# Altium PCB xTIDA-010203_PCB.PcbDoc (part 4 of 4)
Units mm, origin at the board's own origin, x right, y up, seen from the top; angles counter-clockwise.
Board outline 200 x 130 mm, 4 copper layers (Top Layer, Signal Layer 1, Signal Layer 2, Bottom Layer), stack 1.588 mm thick; 249 components, 140 nets, 768 pads, 520 vias.
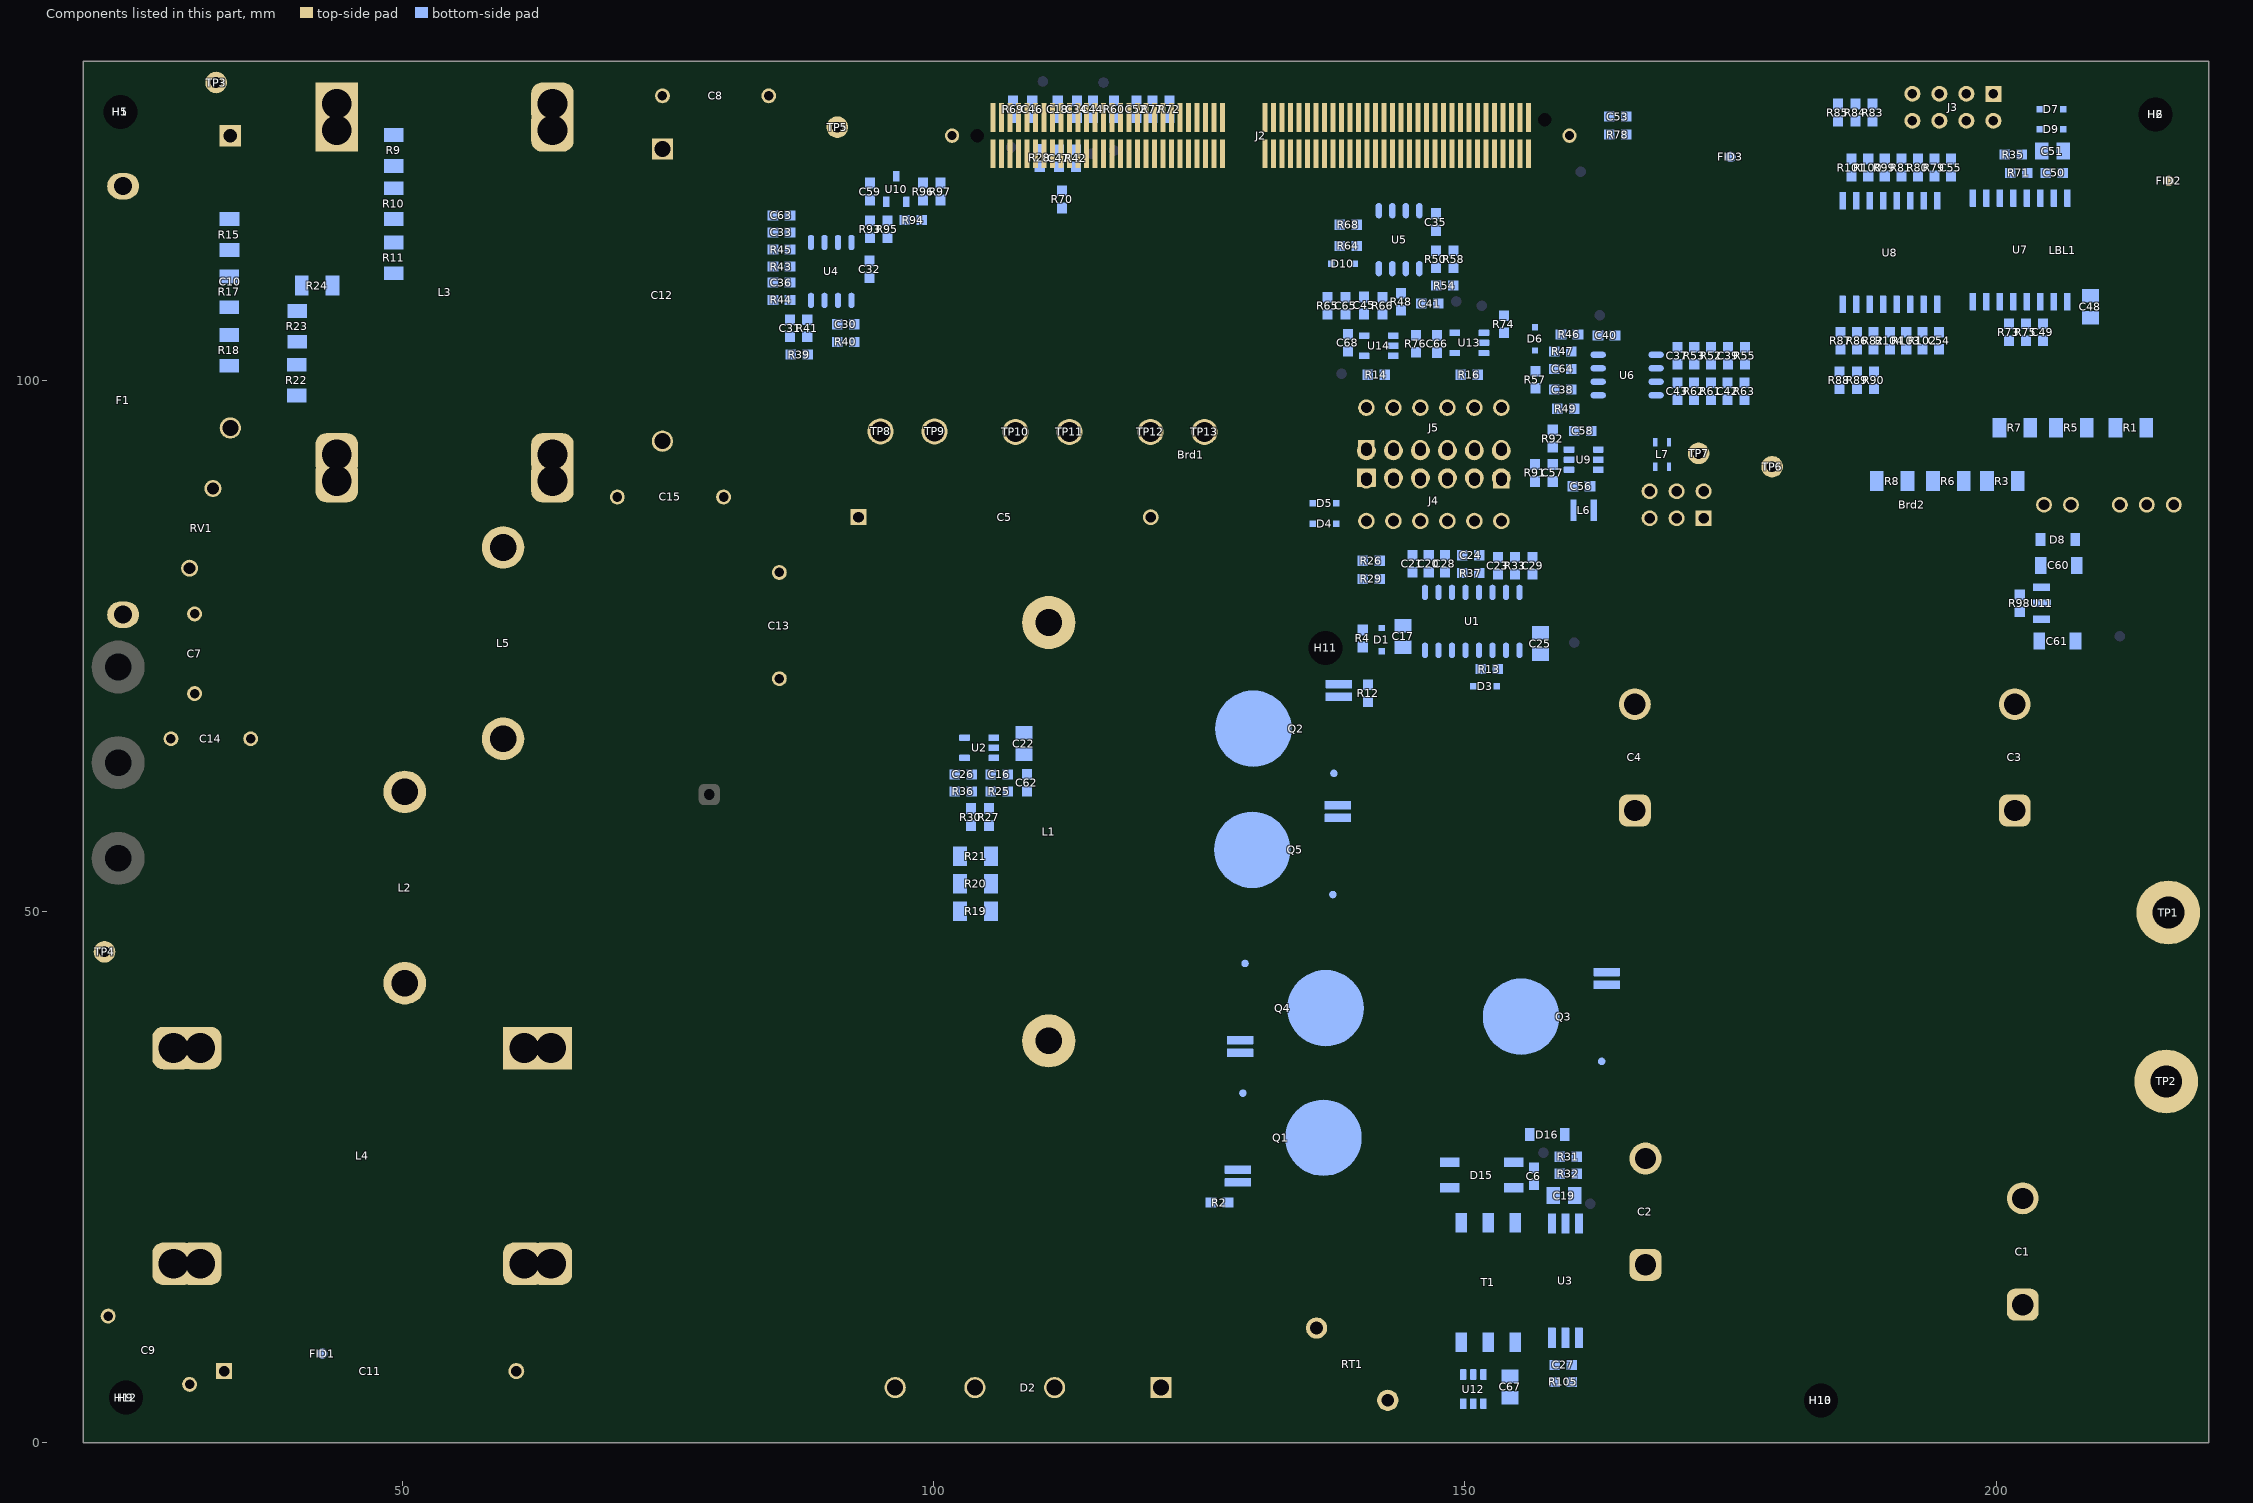
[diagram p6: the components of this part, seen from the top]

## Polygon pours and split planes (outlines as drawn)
NetD2_2 on Bottom Layer "BOTTOM_LAYER_NETD2_2_P189" (solid, remove dead copper, pour order 189): 134.3,76 124.4,76 104.8,56.4 104.8,17.083 108.444,4 115,4 115,12.4 130.2,27.6 130.2,47.2 134.3,51.3
NetC7_1 on Bottom Layer "BOTTOM_LAYER_NETC7_1_P096" (solid, remove dead copper, pour order 96): 20.5,83.5 23.1,86.1 29.9,86.1 32,84 32,77.9 24.5,70.4 20.5,70.4
GND-c on Bottom Layer "BOTTOM_LAYER_GND-C_P219" (solid, remove dead copper, pour order 219): 54.3,20.1 59.2,25 66,25 74.9,33.9 74.9,66.8 83.1,75 100.4,75 103.3,72.1 103.3,18.1 98,12.8 77.7,12.8 68.9,4 57.2,4 54.3,6.9
B+ on Bottom Layer "BOTTOM_LAYER_B+_P197" (solid, remove dead copper, pour order 197): 164.5,10.707 175.493,10.707 175.6,10.752 207.9,10.752 207.9,18.001 201.032,17.998 198,21.03 198,26 200.1,28.1 217.1,28.1 219,30 219,40.497 210.691,40.509 208,43.2 208,62.5 163.5,62.5 162.7,61.7 162.7,33 167.997,33 172,28.997 172,25 167.9,20.9 164.5,20.9
B- on Bottom Layer "BOTTOM_LAYER_B-_P193" (solid, remove dead copper, pour order 193): 137.05,50.004 159.396,50.004 159.396,62.096 163.3,66 207.9,66 208,65.9 208,72 207,73 158.492,73 137.05,69.642
B1+ on Bottom Layer "BOTTOM_LAYER_B1+_P187" (solid, remove dead copper, pour order 187): 159.466,47 159.466,32.813 158.653,32 148.6,32 144.9,28.3 144.9,12.9 134.9,2.9 119.1,2.9 119.1,9.3 132.7,22.9 132.7,46.8 132.9,47
AC-L on Bottom Layer "BOTTOM_LAYER_AC-L_P122" (solid, remove dead copper, pour order 122): 27,21 36,21 38,19 38,4 36,2 29,2 27,4 27,14.002 25.002,16 25.002,19.002
no net on Bottom Layer "BOTTOM_LAYER_NONET_P120" (solid, remove dead copper, pour order 120): 24.033,40
NetL2_2 on Bottom Layer "BOTTOM_LAYER_NETL2_2_P119" (solid, remove dead copper, pour order 119): 51.9,47.031 31.056,47.031 24.9,40.875 24.9,32.2 26.1,31 43,31 53,41 53,46
NetC8_1 on Bottom Layer "BOTTOM_LAYER_NETC8_1_P116" (solid, remove dead copper, pour order 116): 59.1,116 78,116 78,128 77,129 61.1,129 59.1,127
NetC8_1 on Bottom Layer "BOTTOM_LAYER_NETC8_1_P115" (solid, remove dead copper, pour order 115): 49.9,86.9 49.9,103.4 62.5,103.4 62.5,100.1 58.2,95.8 58.2,91.3 54,87.1 54,56.8 53.1,55.9 44,55.9 44,81
NetL4_1 on Bottom Layer "BOTTOM_LAYER_NETL4_1_P118" (solid, remove dead copper, pour order 118): 59,70.048 67.952,70.048 70,68 70,37 66.1,33.1 58.9,33.1 57.4,34.6 57.4,68.5 58.9,70
NetC10_2 on Bottom Layer "BOTTOM_LAYER_NETC10_2_P111" (solid, remove dead copper, pour order 111): 21,58.1 27.279,58.1 34.7,65.521 34.7,85.257 29.995,89.962 29.995,97 45,97 46.3,95.7 46.3,88.5 40.6,82.8 40.6,57.6 35.6,52.6 21,52.6
NetC12_2 on Bottom Layer "BOTTOM_LAYER_NETC12_2_P108" (solid, remove dead copper, pour order 108): 57.4,85.8 61.8,90.2 61.8,95.5 63.2,96.9 74.1,96.9 76,95 76,92.1 64.9,81 57.4,81
NetC10_1 on Bottom Layer "BOTTOM_LAYER_NETC10_1_P103" (solid, remove dead copper, pour order 103): 21,114.8 21,121 29,129 46.1,129 47,128.1 47,120 41.8,114.8
B- on Bottom Layer "BOTTOM_LAYER_B-_P093" (solid, remove dead copper, pour order 93): 134.304,33.019
GND-c on Signal Layer 2 "SIGNAL_LAYER_2_GND-C_P195" (solid, remove dead copper, pour order 195): 128.9,19.1 128.9,63.706 134,68.806 134,82 125,82 123,80 115.7,72.7 80.8,72.7 75,66.9 75,34 66,25 59,25 57,23 57,5.2 58.2,4 74,4 89.1,19.1
NetC7_1 on Signal Layer 2 "SIGNAL_LAYER_2_NETC7_1_P097" (solid, remove dead copper, pour order 97): 20.5,83.5 23.1,86.1 29.9,86.1 32,84 32,77.9 24.5,70.4 20.5,70.4
B1+ on Signal Layer 2 "SIGNAL_LAYER_2_B1+_P221" (solid, remove dead copper, pour order 221): 159.5,37.9 159.5,67.6 155.2,71.9 140,71.9 132.5,64.4 132.5,24.9 135.4,22 150.8,22 159.4,30.6
B- on Signal Layer 2 "SIGNAL_LAYER_2_B-_P199" (solid, remove dead copper, pour order 199): 164,26 164,52.8 170.3,59.1 170.3,62.5 166.8,66 163,66 161.2,67.8 161.2,72 208.7,72 208.7,65.5 199.5,65.5 198,64 198,41.4 207,32.4 207,17 173,17
AGND-s on Signal Layer 2 "SIGNAL_LAYER_2_AGND-S_P173" (solid, remove dead copper, pour order 173): 183.5,129 209,129 210,128 210,116.047 209,115.047 184.842,115.047 183.5,116.389
NetL2_2 on Signal Layer 2 "SIGNAL_LAYER_2_NETL2_2_P130" (solid, remove dead copper, pour order 130): 51.9,47.031 31.056,47.031 24.9,40.875 24.9,32.2 26.1,31 43,31 53,41 53,46
NetL4_1 on Signal Layer 2 "SIGNAL_LAYER_2_NETL4_1_P129" (solid, remove dead copper, pour order 129): 59,70.048 67.952,70.048 70,68 70,35.1 68,33.1 58.9,33.1 57.4,34.6 57.4,68.5 58.9,70
NetC8_1 on Signal Layer 2 "SIGNAL_LAYER_2_NETC8_1_P114" (solid, remove dead copper, pour order 114): 61.1,129 77,129 78,128 78,115.6 78,107.5 69,98.5 63.3,98.5 60.5,95.7 60.5,90.7 56,86.2 56,58.8 53.1,55.9 45.1,55.9 43,58 43,83.1 47.7,87.8 47.7,106.7 59.1,118.1 59.1,127
NetC10_2 on Signal Layer 2 "SIGNAL_LAYER_2_NETC10_2_P110" (solid, remove dead copper, pour order 110): 21,60 28,60 34,66 34,85.957 29.995,89.962 29.995,97 45,97 46.3,95.7 46.3,88.5 41.9,84.1 41.9,55.9 36,50 21,50
NetC12_2 on Signal Layer 2 "SIGNAL_LAYER_2_NETC12_2_P107" (solid, remove dead copper, pour order 107): 57.4,85.8 61.8,90.2 61.8,95.5 63.2,96.9 75,96.9 76,95.9 76,89.9 67.1,81 57.4,81
NetC10_1 on Signal Layer 2 "SIGNAL_LAYER_2_NETC10_1_P102" (solid, remove dead copper, pour order 102): 21,114.8 21,121 29,129 46.1,129 47,128.1 47,120 41.8,114.8
NetC7_1 on Top Layer "TOP_LAYER_NETC7_1_P098" (solid, remove dead copper, pour order 98): 20.5,83.5 23.1,86.1 29.9,86.1 32,84 32,77.9 24.5,70.4 20.5,70.4
AGND-s on Top Layer "TOP_LAYER_AGND-S_P171" (solid, remove dead copper, pour order 171): 183.5,129 209,129 210,128 210,116.047 209,115.047 184.842,115.047 183.5,116.389
GND-c on Top Layer "TOP_LAYER_GND-C_P167" (solid, remove dead copper, pour order 167): 91.204,127.254 177.5,127.254 177.5,114.7 182.8,109.4 210.934,109.4 212.1,108.234 212.1,99.2 210,97.1 203.6,97.1 186.5,80 129.461,80 128.961,80.5 128.961,87.961 131.7,90.7 131.7,96.978 126.678,102 86,102 85,103 85,121.05
B1+ on Top Layer "TOP_LAYER_B1+_P185" (solid, remove dead copper, pour order 185): 98.4,35.4 90.1,43.7 90.1,89.145 91.055,90.1 99.2,90.1 102.5,86.8 102.5,74.1 114.7,61.9 159.4,61.9 159.4,35.4
B- on Top Layer "TOP_LAYER_B-_P229" (solid, remove dead copper, pour order 229): 133.7,16.7 158.7,16.7 163.3,21.3 169,21.3 172.6,17.7 207,17.7 207,32.231 197,42.231 197,61.4 201,65.4 208.7,65.4 208.7,72 161.2,72 161.2,67.8 161.9,67.1 164.8,67.1 170.5,61.4 170.5,57.5 163.6,50.6 163.6,34.6 160.9,31.9 99.1,31.9 93,25.8 93,3.05 93.9,2.15 99.55,2.15 100,2.6 100,6.6 105.1,11.7 128.7,11.7
GND-c on Top Layer "TOP_LAYER_GND-C_P211" (solid, remove dead copper, pour order 211): 66.3,22 57.3,22 54.3,19 54.3,4 56.3,2 63.3,2 65.3,4 65.3,14.002 67.298,16 67.298,21.002
AC-L on Top Layer "TOP_LAYER_AC-L_P123" (solid, remove dead copper, pour order 123): 26,22 35,22 38,19 38,4 36,2 29,2 27,4 27,14.002 25.002,16 25.002,21.002
NetL2_2 on Top Layer "TOP_LAYER_NETL2_2_P121" (solid, remove dead copper, pour order 121): 51.9,47.031 31.031,47.031 24.9,40.9 24.9,31 42.9,31 53,41.1 53,46
NetL4_1 on Top Layer "TOP_LAYER_NETL4_1_P117" (solid, remove dead copper, pour order 117): 59,70.048 67.952,70.048 70,68 70,35.1 68,33.1 58.9,33.1 57.4,34.6 57.4,68.5 58.9,70
NetC10_2 on Top Layer "TOP_LAYER_NETC10_2_P109" (solid, remove dead copper, pour order 109): 21,58.1 27.279,58.1 34.7,65.521 34.7,85.257 29.995,89.962 29.995,97 45,97 46.3,95.7 46.3,88.5 40.6,82.8 40.6,57.6 35.6,52.6 21,52.6
NetC12_2 on Top Layer "TOP_LAYER_NETC12_2_P105" (solid, remove dead copper, pour order 105): 57.4,85.8 61.8,90.2 61.8,95.5 63.2,96.9 74.1,96.9 76,95 76,93.067 63.933,81 57.4,81
NetC8_1 on Top Layer "TOP_LAYER_NETC8_1_P104" (solid, remove dead copper, pour order 104): 61.1,129 77,129 78,128 78,115.6 61.9,99.5 58.2,95.8 58.2,91.3 54.1,87.2 54.1,56.9 53.1,55.9 45.1,55.9 44,57 44,81 49.8,86.8 49.8,108.8 59.1,118.1 59.1,127
NetC10_1 on Top Layer "TOP_LAYER_NETC10_1_P100" (solid, remove dead copper, pour order 100): 21,114.8 21,121 29,129 46.1,129 47,128.1 47,120 41.8,114.8
NetC7_1 on Signal Layer 1 "SIGNAL_LAYER_1_NETC7_1_P099" (solid, remove dead copper, pour order 99): 20.5,83.5 23.1,86.1 29.9,86.1 32,84 32,77.9 24.5,70.4 20.5,70.4
GND-c on Signal Layer 1 "SIGNAL_LAYER_1_GND-C_P165" (solid, remove dead copper, pour order 165): 128.9,99.3 126.2,102 86,102 85,103 85,123.05 90.95,129 176.8,129 177.9,127.9 177.9,114.3 182.8,109.4 212,109.4 212,97.1 203.7,97.1 198.6,92 194,92 182.011,80.011 129.75,80.011 128.9,80.861
B1+ on Signal Layer 1 "SIGNAL_LAYER_1_B1+_P209" (solid, remove dead copper, pour order 209): 159.6,65.5 111.1,65.5 102.5,74.1 102.5,86.9 99.3,90.1 91.055,90.1 90.1,89.145 90.1,65.5 108.148,47.452 114.748,47.452 120.1,42.1 120.1,27 117.1,24 117.1,2.9 131.9,2.9 159.6,30.6
NetC10_2 on Signal Layer 1 "SIGNAL_LAYER_1_NETC10_2_P217" (solid, remove dead copper, pour order 217): 29.995,89.962 32.957,87 44.5,87 46.3,88.8 46.3,95.7 45,97 29.995,97
GND-c on Signal Layer 1 "SIGNAL_LAYER_1_GND-C_P215" (solid, remove dead copper, pour order 215): 68,20 58,20 57,19 57,4 59,2 66,2 68,4 68,14.002
B+ on Signal Layer 1 "SIGNAL_LAYER_1_B+_P201" (solid, remove dead copper, pour order 201): 164,13 164,19.6 170.3,25.9 170.3,29.8 161.2,38.9 161.2,65.1 202,65.1 209,58.1 209,28 203,28 200,25 200,21.05 208,13.05 208,9 174,9 168,9
AGND-s on Signal Layer 1 "SIGNAL_LAYER_1_AGND-S_P169" (solid, remove dead copper, pour order 169): 183.5,129 209,129 210,128 210,116.047 209,115.047 184.842,115.047 183.5,116.389
AC-L on Signal Layer 1 "SIGNAL_LAYER_1_AC-L_P125" (solid, remove dead copper, pour order 125): 91.1,2 106.7,2 106.7,21.7 117,32 117,41 114,44 105.1,44 92.1,31 48,31 39,22 26,22 26,2 37.7,2 58.1,22.4 81.2,22.4 91.1,12.5
NetL2_2 on Signal Layer 1 "SIGNAL_LAYER_1_NETL2_2_P131" (solid, remove dead copper, pour order 131): 51.9,47.031 33.031,47.031 26,40 26,32.9 27.9,31 43,31 53,41 53,46
NetL4_1 on Signal Layer 1 "SIGNAL_LAYER_1_NETL4_1_P128" (solid, remove dead copper, pour order 128): 59,70.048 67.952,70.048 70,68 70,35.1 68,33.1 58.9,33.1 57.4,34.6 57.4,68.5 58.9,70
NetC8_1 on Signal Layer 1 "SIGNAL_LAYER_1_NETC8_1_P113" (solid, remove dead copper, pour order 113): 43,58 43,71 54.9,71 54.9,57.7 53.1,55.9 45.1,55.9
NetC8_1 on Signal Layer 1 "SIGNAL_LAYER_1_NETC8_1_P112" (solid, remove dead copper, pour order 112): 43,81.1 43,76 54.9,76 54.9,86.9 59.1,91.1 59.1,96.7 61.9,99.5 70,99.5 78,107.5 78,115.6 78,128 77,129 61.1,129 59.1,127 59.1,118.1 49,108 49,87.1
NetC12_2 on Signal Layer 1 "SIGNAL_LAYER_1_NETC12_2_P106" (solid, remove dead copper, pour order 106): 57.4,85.8 61.8,90.2 61.8,95.5 63.2,96.9 75,96.9 76,95.9 76,89.9 67.1,81 57.4,81
NetC10_1 on Signal Layer 1 "SIGNAL_LAYER_1_NETC10_1_P101" (solid, remove dead copper, pour order 101): 21,114.8 21,121 29,129 46.1,129 47,128.1 47,120 41.8,114.8

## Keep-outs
Keep-Out Layer:
  text ".Layer_Name" at 14.656,-21.806 h1.52

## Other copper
Top Layer:
  pour cut-out: 129.1,35.649 ccw(c130.1,35.649) 130.1,34.649 ccw(c130.1,35.649) 131.1,35.649 ccw(c130.1,35.649) 130.1,36.649 ccw(c130.1,35.649)
  pour cut-out: 128.301,35.4 ccw(c129.301,35.4) 129.301,34.4 ccw(c129.301,35.4) 130.301,35.4 ccw(c129.301,35.4) 129.301,36.4 ccw(c129.301,35.4)
  pour cut-out: 106.35,37.77 ccw(c110.85,37.77) 110.85,33.27 ccw(c110.85,37.77) 115.35,37.77 ccw(c110.85,37.77) 110.85,42.27 ccw(c110.85,37.77)
  pour cut-out: 106.35,77.14 ccw(c110.85,77.14) 110.85,72.64 ccw(c110.85,77.14) 115.35,77.14 ccw(c110.85,77.14) 110.85,81.64 ccw(c110.85,77.14)
  text ".Layer_Name" at 14.656,-21.806 h1.52
Signal Layer 1:
  rectangle net NetC8_1: 43.3,66 54.8,70.7
  rectangle net NetC8_1: 43.3,76.7 54.6,81.1
Signal Layer 2:
  rectangle net NetC8_1: 43.3,65.9 54.6,81.1
Bottom Layer:
  pour cut-out: 106.35,37.852 ccw(c110.85,37.852) 110.85,33.351 ccw(c110.85,37.852) 115.35,37.852 ccw(c110.85,37.852) 110.85,42.352 ccw(c110.85,37.852)
  region net ANA_Iac: 110.8,125.9
  region: 110.2,121.7
  text ".Layer_Name" at 14.656,-21.806 h1.52

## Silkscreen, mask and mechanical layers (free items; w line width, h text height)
Top Overlay:
  text "250VAC,20A" at 25.9,126.1 h1.85 r270
  text "TIDA-010203 E003" at 173.68,111.3 h2.75
  text "2021.10" at 185.882,105.997 h2.75
  text "L" at 25.5,76.2 h3 r270
  text "PE" at 25.3,69.2 h3 r270
  text "N" at 25.2,58.5 h3 r270
  text "B-" at 212.3,44.5 h5 r90
  text "B+" at 212.3,35 h5 r90
  text ".Layer_Name" at 14.656,-21.806 h1.52
Bottom Overlay:
  lines w0.2: 185,109.1 185,115.5 195,115.5 195,109.9 194.2,109.1 185,109.1 ; 197.3,109.1 206.5,109.1 207.3,109.9 207.3,115.5 197.3,115.5 197.3,109.1
  text "B+" at 99.4,90.4 h2
  text "SW" at 111.2,90.4 h2
  text "B-" at 123.9,90.4 h2
  text "B+" at 217.5,90.1 h1.85
  text "B-" at 207.746,89.7 h1.85
  text "12VL" at 202.935,87 h1.85
  text "12Vc" at 169.5,81.736 h1.85 r270
  text "GNDc" at 167,81.5 h1.85 r270
  text "ACL" at 27.1,71.5 h2 r270
  text "PE" at 27.4,61.5 h2 r270
  text "ACN" at 26.7,51.8 h2 r270
  text "B-" at 208.9,48.5 h2 r270
  text "B+" at 209.4,33 h2 r270
  text ".Layer_Name" at 14.656,-21.806 h1.52
Top Paste:
  text ".Layer_Name" at 14.656,-21.806 h1.52
Bottom Paste:
  text ".Layer_Name" at 14.656,-21.806 h1.52
Top Solder:
  text ".Layer_Name" at 14.656,-21.806 h1.52
  text ".Layer_Name" at 14.656,-21.806 h1.52
Bottom Solder:
  region: 178.3,71.9 178.3,66.9 188.3,66.9 188.3,71.9
  region: 142.4,14.8 142.4,19.8 132.4,19.8 132.4,14.8
  rectangle: 143.8,35.6 148.8,45.6
  rectangle: 149.74,55.4 154.74,65.4
  rectangle: 142.9,57.1 147.9,67.1
  rectangle: 110.9,46.9 115.9,56.9
  rectangle: 111.2,18.1 116.2,28.1
  rectangle: 118.1,28.7 123.1,38.7
  rectangle: 117.8,43 122.8,53
  rectangle: 117.8,56.7 122.8,66.7
  text ".Layer_Name" at 14.656,-21.806 h1.52
Drill Guide:
  text ".Layer_Name" at 14.656,-21.806 h1.52
M1 Board Outline:
  the board outline again, w0.254
  text ".Layer_Name" at 14.656,-21.806 h1.52
M2 Board Dimensions:
  rectangle: 3.175,-10.16 12.7,-6.985
  rectangle: 0,-6.985 3.175,-3.81
  lines w0.178: 0,-6.985 25.4,-6.985 ; 3.175,-10.16 3.175,-3.81 ; 6.35,-10.16 6.35,-3.81 ; 12.7,-10.16 12.7,-3.81 ; 19.05,-10.16 19.05,-3.81 ; 0,-10.16 0,-3.81 25.4,-3.81 25.4,-10.16 0,-10.16
  text ".Layer_Name" at 14.656,-21.806 h1.52
M3 3D STEP Top:
  text ".Layer_Name" at 14.656,-21.806 h1.52
M4 3D STEP Bottom:
  text ".Layer_Name" at 14.656,-21.806 h1.52
M5 Assembly Top:
  lines w0.254: -7.417,-23.626 160.223,-23.626 ; -7.417,-18.462 160.274,-18.462 ; -7.417,-13.297 -7.417,-28.791 94.31,-28.791 160.274,-28.791 160.274,-13.297 -7.404,-13.297 -7.404,-28.791 32.614,-28.791 ; 55.194,-28.791 55.194,-13.297 ; 87.376,-18.462 87.376,-13.297 ; 108.712,-18.462 108.712,-13.297 ; 124.511,-28.956 124.511,-23.804
  text "COMPONENTS MARKED 'DNP' SHOULD NOT BE POPULATED." at 29.299,-8.09 h1.52
  text "ASSEMBLY VARIANT:" at 29.286,-11.024 h1.52
  text ".VariantName" at 55.601,-11.024 h1.52
  text "PCB VIEWED FROM TOP SIDE" at -5.804,-16.654 h1.52
  text "BOARD #:" at 57.099,-16.654 h1.52
  text ".PRJ_Number" at 70.955,-16.654 h1.52
  text "REV:" at 92.405,-16.654 h1.52
  text ".PCB_Rev" at 99.809,-16.654 h1.52
  text "SVN REV:" at 113.69,-16.654 h1.52
  text ".VersionControl_RevNumber" at 126.543,-16.654 h1.52
  text "TID #:" at 57.099,-21.819 h1.52
  text ".TID" at 70.955,-21.819 h1.52
  text "PLOT NAME =" at -5.804,-27.034 h1.52
  text ".plot_File_Name" at 14.656,-27.034 h1.52
  text "GENERATED    :" at 57.15,-27.034 h1.52
  text ".Print_Date" at 79.235,-27.034 h1.52
  text ".Print_Time" at 97.752,-27.034 h1.52
  text "TEXAS INSTRUMENTS" at 129.87,-27.034 h1.52
M6 Assembly Bottom:
  lines w0.254: -7.429,-18.474 160.261,-18.474 ; -7.379,-23.639 160.261,-23.639 ; 28.334,-28.969 28.334,-23.817 ; 44.133,-18.474 44.133,-13.31 ; 65.468,-18.474 65.468,-13.31 ; 97.65,-28.804 97.65,-13.31 ; 120.231,-28.804 160.249,-28.804 160.249,-13.31 -7.429,-13.31 -7.429,-28.804 58.534,-28.804 160.261,-28.804 160.261,-13.31
  text "COMPONENTS MARKED 'DNP' SHOULD NOT BE POPULATED." at 154.991,-8.077 h1.52
  text ".VariantName" at 128.473,-11.024 h1.52
  text "ASSEMBLY VARIANT:" at 154.864,-11.024 h1.52
  text ".VersionControl_RevNumber" at 26.302,-16.667 h1.52
  text "SVN REV:" at 39.154,-16.667 h1.52
  text ".PCB_Rev" at 53.035,-16.667 h1.52
  text "REV:" at 60.439,-16.667 h1.52
  text ".PRJ_Number" at 81.89,-16.667 h1.52
  text "BOARD #:" at 95.745,-16.667 h1.52
  text "PCB VIEWED FROM BOTTOM SIDE" at 158.648,-16.667 h1.52
  text ".TID" at 81.89,-21.831 h1.52
  text "TID #:" at 95.745,-21.831 h1.52
  text "TEXAS INSTRUMENTS" at 22.974,-27.047 h1.52
  text ".Print_Time" at 55.093,-27.047 h1.52
  text ".Print_Date" at 73.609,-27.047 h1.52
  text "GENERATED    :" at 95.694,-27.047 h1.52
  text ".plot_File_Name" at 138.189,-27.047 h1.52
  text "PLOT NAME =" at 158.648,-27.047 h1.52
M9 Title Sheet:
  drawing of 57 lines, arcs and shapes, not listed
  text "1" at 18.792,204.127 h1.78
  text "2" at 82.182,204.127 h1.78
  text "3" at 145.411,204.127 h1.78
  text "4" at 209.08,204.127 h1.78
  text "5" at 272.555,204.127 h1.78
  text "6" at 336.182,204.127 h1.78
  text "A" at -10.579,175.095 h1.78
  text "A" at 365.341,175.095 h1.78
  text "B" at -10.579,114.643 h1.78
  text "B" at 365.341,114.643 h1.78
  text "C" at -10.579,54.318 h1.78
  text "C" at 365.341,54.318 h1.78
  text "PROJECT TITLE:" at 288.125,7.048 h1.14
  text ".PRJ_Title" at 289.395,3.662 h1.78
  text "DESIGNED FOR:" at 288.125,-0.597 h1.14
  text ".PRJ_Customer" at 289.395,-4.153 h1.78
  text "D" at -10.579,-5.88 h1.78
  text "D" at 365.341,-5.88 h1.78
  text "FILE NAME:" at 288.125,-8.217 h1.14
  text ".PCB_File_Name_No_Path" at 289.395,-11.265 h1.78
  text "Texas Instruments (TI) and/or its licensors do not warrant the accuracy or completeness of this specification" at 161.9,-15.376 h1.14
  text "ENGINEER:" at 288.125,-15.583 h1.14
  text "LAYOUT BY:" at 326.352,-15.583 h1.14
  text "or any information contained therein. TI and/or its licensors do not warrant that this design will meet" at 160.757,-18.237 h1.14
  text ".PRJ_Engineer" at 289.395,-19.52 h1.78
  text ".PCB_Layout" at 327.635,-19.52 h1.78
  text "the specifications, will be suitable for your application or fit for any particular purpose, or will operate in" at 160.757,-21.099 h1.14
  text ".Layer_Name" at 14.656,-21.806 h1.52
  text "ALTIUM DESIGNER VERSION:" at 326.352,-23.457 h1.14
  text "an implementation. TI and/or its licensors do not warrant that the design is production worthy. You should" at 160.757,-23.961 h1.14
  text "completely validate and test your design implementation to confirm the system functionality for your application." at 161.9,-26.822 h1.14
  text ".print_Scale" at 289.395,-26.843 h1.78
  text ".Application_BuildNumber" at 327.635,-26.843 h1.78
  text "1" at 18.792,-32.093 h1.78
  text "2" at 82.182,-32.093 h1.78
  text "3" at 145.411,-32.093 h1.78
  text "4" at 209.08,-32.093 h1.78
  text "5" at 272.555,-32.093 h1.78
  text "6" at 336.182,-32.093 h1.78
M10 Fab Notes:
  drawing of 189 lines, arcs and shapes, not listed
  text "DESIGN INFORMATION" at 314.503,161.447 h1.52
  text "MIN. TRACK WIDTH:" at 298.131,158.091 h1.52
  text "8" at 325.976,158.091 h1.52
  text "MIL" at 329.907,158.091 h1.52
  text "MIN. CLEARANCE:" at 298.131,154.938 h1.52
  text "0.2" at 324.452,154.938 h1.52
  text "mm" at 329.907,154.938 h1.52
  text "MIN. VIA PAD SIZE:" at 298.131,151.785 h1.52
  text "24" at 325.214,151.785 h1.52
  text "MIL" at 329.907,151.785 h1.52
  text "0.05mm (2MIL)" at 315.784,148.486 h1.52
  text "MINIMUM ANNULAR RING" at 289.769,148.277 h1.52
  text "EXTERNAL" at 333.768,148.277 h1.52
  text "PER" at 294.849,145.48 h1.52
  text "IPC-D-275 CLASS 2 LEVEL C" at 300.437,145.48 h1.52
  text "MIL, HOLES" at 338.238,142.928 h1.52
  text "+/-" at 328.27,142.709 h1.52
  text "+/-" at 349.961,142.709 h1.52
  text "REGISTRATION TOLERANCES:" at 289.769,142.682 h1.52
  text "METAL" at 320.243,142.682 h1.52
  text "5" at 334.879,142.683 h1.52
  text "3" at 356.037,142.683 h1.52
  text "MIL" at 358.99,142.682 h1.52
  text "HOLE SIZE TOLERANCE (UNLESS OTHERWISE SPECIFIED):" at 289.769,140.185 h1.52
  text "+/-" at 349.961,140.112 h1.52
  text "3" at 356.037,140.085 h1.52
  text "MIL" at 358.99,140.085 h1.52
  text "MATERIAL:" at 287.87,136.589 h1.52
  text "FR-4 High Tg" at 312.926,133.324 h1.52
  text "X" at 309.257,133.122 h1.52
  text "FR-408" at 298.563,133.007 h1.52
  text "OTHER" at 336.358,133.007 h1.52
  text "62 MIL (1.6mm) +/-10%" at 306.694,129.374 h1.52
  text "X" at 303.643,129.312 h1.52
  text "THICKNESS:" at 289.769,129.165 h1.52
  text "OTHER" at 339.33,129.165 h1.52
  text "TOLERANCE:" at 289.769,125.652 h1.52
  text "X" at 311.314,125.652 h1.52
  text "ANSI IPC-6012 TYPE 3 CLASS 2" at 315.836,125.652 h1.52
  text "OTHER +/-" at 315.835,121.989 h1.52
  text "BOW & TWIST:" at 289.769,118.302 h1.52
  text "X" at 311.314,118.302 h1.52
  text "ANSI IPC-6012 TYPE 3 CLASS 2" at 315.836,118.302 h1.52
  text "OTHER +/-" at 315.835,114.576 h1.52
  text "DRILLING:" at 287.87,111.258 h1.52
  text "NC_DRILL FILES" at 332.599,108.586 h1.52
  text "REFERENCE:" at 289.769,108.486 h1.52
  text "X" at 306.463,108.484 h1.52
  text "AS SHOWN" at 310.984,108.486 h1.52
  text "X" at 329.348,108.486 h1.52
  text "OTHER" at 340.168,104.873 h1.52
  text "PTH COPPER THICKNESS:" at 289.761,104.783 h1.52
  text "X" at 318.697,104.783 h1.52
  text "20-30 um" at 321.948,104.783 h1.52
  text "BOARD FINISH:" at 287.87,101.034 h1.52
  text "SILKSCREEN:" at 291.812,98.237 h1.52
  text "X" at 316.14,98.237 h1.52
  text "TOP" at 319.112,98.237 h1.52
  text "X" at 329.094,98.237 h1.52
  text "BOTTOM" at 332.091,98.237 h1.52
  text "SILKSCREEN COLOR:" at 291.812,94.295 h1.52
  text "X" at 316.115,94.295 h1.52
  text "WHITE" at 319.112,94.295 h1.52
  text "OTHER" at 332.091,94.295 h1.52
  text "X" at 319.442,90.652 h1.52
  text "GREEN" at 322.439,90.652 h1.52
  text "OTHER" at 338.136,90.652 h1.52
  text "SOLDER RESIST COLOR:" at 291.812,90.477 h1.52
  text "X" at 319.442,86.734 h1.52
  text "MATTE" at 322.439,86.734 h1.52
  text "SEMI-GLOSS" at 338.125,86.717 h1.52
  text "IMMERSION GOLD (ENIG)" at 314.819,82.345 h1.52
  text "ENEPIG" at 348.793,82.162 h1.52
  text "SURFACE FINISH:" at 287.87,82.136 h1.52
  text "X" at 310.298,82.136 h1.52
  text "IMM. TIN/SILVER OR EQUIV" at 296.24,78.649 h1.52
  text "OTHER" at 332.599,78.549 h1.52
  text "ARRAY/PANEL:" at 287.87,74.602 h1.52
  text "CUT AND TRIM PER M1 BOARD OUTLINE" at 314.819,74.393 h1.52
  text "N.C. ROUTE" at 314.819,70.94 h1.52
  text "X" at 332.295,70.94 h1.52
  text "V. SCORE" at 336.816,70.94 h1.52
  text "CERTIFICATION:" at 287.87,67.66 h1.52
  text "MATERIALS AND WORKMANSHIP FOR ALL PCBS" at 306.285,67.66 h1.52
  text "TO MEET OR EXCEED THE REQUIREMENTS OF:" at 306.285,65.271 h1.52
  text "X" at 297.078,62.003 h1.52
  text "ANSI IPC-A-600F CLASS ->" at 300.329,62.003 h1.52
  text "X" at 342.188,62.003 h1.52
  text "2" at 344.982,62.003 h1.52
  text "1" at 336.981,61.965 h1.52
  text "3" at 353.973,61.965 h1.52
  text "X" at 317.702,58.252 h1.52
  text "RoHS" at 320.953,58.252 h1.52
  text "OTHER" at 337.321,58.252 h1.52
  text "PER ORDER" at 347.407,58.252 h1.52
  text "ALL BOARDS MUST MEET OR EXCEED UL94-V0 REQUIREMENTS." at 288.569,54.345 h1.52
  text "PCB MUST BEAR THE UL94V-0 UL REGISTERED MATERIAL ID NUMBER" at 288.569,51.397 h1.52
  text "ADDITIONAL REQUIREMENTS:" at 287.87,47.094 h1.52
  text "MICROSECTION:" at 289.769,44.373 h1.52
  text "YES" at 312.775,44.373 h1.52
  text "REQUIRED" at 334.657,40.707 h1.52
  text "BARE BOARD ELEC. TEST:" at 289.769,40.634 h1.52
  text "NONE" at 322.935,40.634 h1.52
  text "X" at 331.66,40.634 h1.52
  text "PER ORDER" at 349.693,40.634 h1.52
  text "XX MIL VIAS REQUIRE NON-CONDUCTIVE FILL AND PLANARIZE" at 294.04,35.428 h1.5
  text "XX MIL VIAS REQUIRE CONDUCTIVE FILL AND PLANARIZE" at 294.243,32.787 h1.52
  text "OUTER XX MIL TRACES REQUIRE 50 OHM SINGLE-ENDED IMPEDANCE" at 294.218,28.637 h1.47
  text "LAYER 2 & 3 (INNER LAYERS) XX MIL WIDE, XX MIL SPACE / TRACES REQUIRE 100 OHM DIFFERENTIAL IMPEDANCE" at 294.015,22.65 h1.52
  text ".Layer_Name" at 14.656,-21.806 h1.52
M11 Gerber Information:
  lines w0.254: -7.417,-23.626 160.223,-23.626 ; -7.417,-18.462 160.274,-18.462 ; -7.417,-13.297 -7.417,-28.791 94.31,-28.791 160.274,-28.791 160.274,-13.297 -7.404,-13.297 -7.404,-28.791 32.614,-28.791 ; 55.194,-28.791 55.194,-13.297 ; 87.376,-18.462 87.376,-13.297 ; 108.712,-18.462 108.712,-13.297 ; 124.511,-28.956 124.511,-23.804
  text "ALL ARTWORK VIEWED FROM TOP SIDE" at -5.804,-16.654 h1.52
  text "BOARD #:" at 57.099,-16.654 h1.52
  text ".PRJ_Number" at 70.955,-16.654 h1.52
  text "REV:" at 92.405,-16.654 h1.52
  text ".PCB_Rev" at 99.809,-16.654 h1.52
  text "SVN REV:" at 113.69,-16.654 h1.52
  text ".VersionControl_RevNumber" at 126.543,-16.654 h1.52
  text "LAYER NAME =" at -5.804,-21.806 h1.52
  text "TID #:" at 57.099,-21.819 h1.52
  text ".TID" at 70.955,-21.819 h1.52
  text "PLOT NAME =" at -5.804,-27.034 h1.52
  text ".plot_File_Name" at 14.656,-27.034 h1.52
  text "GENERATED    :" at 57.15,-27.034 h1.52
  text ".Print_Date" at 79.235,-27.034 h1.52
  text ".Print_Time" at 97.752,-27.034 h1.52
  text "TEXAS INSTRUMENTS" at 129.87,-27.034 h1.52
M12 Stackup:
  drawing of 295 lines, arcs and shapes, not listed
  text "Layer" at 247.781,191.495 h1.52
  text "Name" at 258.192,191.495 h1.52
  text "Material" at 282.062,191.495 h1.52
  text "Thickness" at 303.9,191.495 h1.52
  text "Constant" at 320.406,191.495 h1.52
  text "Board Layer Stack" at 334.88,191.495 h1.52
  text "1" at 247.781,188.447 h1.52
  text "Top Overlay" at 258.192,188.447 h1.52
  text "2" at 247.781,185.399 h1.52
  text "Top Solder" at 258.192,185.399 h1.52
  text "Solder Resist" at 282.062,185.399 h1.52
  text "0.010mm" at 303.9,185.399 h1.52
  text "3.5" at 320.406,185.399 h1.52
  text "3" at 247.781,182.351 h1.52
  text "Top Layer" at 258.192,182.351 h1.52
  text "Copper" at 282.062,182.351 h1.52
  text "0.070mm" at 303.9,182.351 h1.52
  text "4" at 247.781,179.303 h1.52
  text "Dielectric1" at 258.192,179.303 h1.52
  text "FR-4" at 282.062,179.303 h1.52
  text "0.254mm" at 303.9,179.303 h1.52
  text "4.5" at 320.406,179.303 h1.52
  text "5" at 247.781,176.255 h1.52
  text "Signal Layer 1" at 258.192,176.255 h1.52
  text "Copper" at 282.062,176.255 h1.52
  text "0.070mm" at 303.9,176.255 h1.52
  text "6" at 247.781,173.207 h1.52
  text "Dielectric 2" at 258.192,173.207 h1.52
  text "FR-4" at 282.062,173.207 h1.52
  text "0.800mm" at 303.9,173.207 h1.52
  text "4.5" at 320.406,173.207 h1.52
  text "7" at 247.781,170.159 h1.52
  text "Signal Layer 2" at 258.192,170.159 h1.52
  text "Copper" at 282.062,170.159 h1.52
  text "0.070mm" at 303.9,170.159 h1.52
  text "8" at 247.781,167.111 h1.52
  text "Dielectric 3" at 258.192,167.111 h1.52
  text "FR-4" at 282.062,167.111 h1.52
  text "0.254mm" at 303.9,167.111 h1.52
  text "4.5" at 320.406,167.111 h1.52
  text "9" at 247.781,164.063 h1.52
  text "Bottom Layer" at 258.192,164.063 h1.52
  text "Copper" at 282.062,164.063 h1.52
  text "0.070mm" at 303.9,164.063 h1.52
  text "10" at 247.781,161.015 h1.52
  text "Bottom Solder" at 258.192,161.015 h1.52
  text "Solder Resist" at 282.062,161.015 h1.52
  text "0.010mm" at 303.9,161.015 h1.52
  text "3.5" at 320.406,161.015 h1.52
  text "11" at 247.781,157.967 h1.52
  text "Bottom Overlay" at 258.192,157.967 h1.52
  text ".Layer_Name" at 14.656,-21.806 h1.52
M13 Component Bodies Top:
  text ".Layer_Name" at 14.656,-21.806 h1.52
M14 Component Bodies Bottom:
  text ".Layer_Name" at 14.656,-21.806 h1.52
M15 Courtyards Top:
  text ".Layer_Name" at 14.656,-21.806 h1.52
M16 Courtyards Bottom:
  text ".Layer_Name" at 14.656,-21.806 h1.52
Drill Drawing:
  drawing of 178 lines, arcs and shapes, not listed
  text "Symbol" at 163.93,198.544 h1.61
  text "Quantity" at 170.638,198.544 h1.61
  text "Finished Hole Size" at 178.047,198.544 h1.61
  text "Plated" at 192.251,198.544 h1.61
  text "Hole Type" at 198.034,198.544 h1.61
  text "Drill Layer Pair" at 206.406,198.544 h1.61
  text "Hole Tolerance" at 222.583,198.544 h1.61
  text "2" at 170.638,195.767 h1.34
  text "50.00mil (1.270mm)" at 178.047,195.767 h1.34
  text "NPTH" at 192.251,195.767 h1.34
  text "Round" at 198.034,195.767 h1.34
  text "Top Layer - Bottom Layer" at 206.406,195.767 h1.34
  text "5" at 170.638,192.99 h1.34
  text "125.98mil (3.200mm)" at 178.047,192.99 h1.34
  text "NPTH" at 192.251,192.99 h1.34
  text "Round" at 198.034,192.99 h1.34
  text "Top Layer - Bottom Layer" at 206.406,192.99 h1.34
  text "430" at 170.638,190.214 h1.34
  text "11.81mil (0.300mm)" at 178.047,190.214 h1.34
  text "PTH" at 192.251,190.214 h1.34
  text "Round" at 198.034,190.214 h1.34
  text "Top Layer - Bottom Layer" at 206.406,190.214 h1.34
  text "F" at 163.344,189.96 h1.23
  text "6" at 170.638,187.437 h1.34
  text "27.56mil (0.700mm)" at 178.047,187.437 h1.34
  text "PTH" at 192.251,187.437 h1.34
  text "Round" at 198.034,187.437 h1.34
  text "Top Layer - Bottom Layer" at 206.406,187.437 h1.34
  text "90" at 170.638,184.661 h1.34
  text "28.00mil (0.711mm)" at 178.047,184.661 h1.34
  text "PTH" at 192.251,184.661 h1.34
  text "Round" at 198.034,184.661 h1.34
  text "Top Layer - Bottom Layer" at 206.406,184.661 h1.34
  text "E" at 163.344,184.407 h1.23
  text "2" at 170.638,181.884 h1.34
  text "33.07mil (0.840mm)" at 178.047,181.884 h1.34
  text "PTH" at 192.251,181.884 h1.34
  text "Round" at 198.034,181.884 h1.34
  text "Top Layer - Bottom Layer" at 206.406,181.884 h1.34
  text "20" at 170.638,179.108 h1.34
  text "35.43mil (0.900mm)" at 178.047,179.108 h1.34
  text "PTH" at 192.251,179.108 h1.34
  text "Round" at 198.034,179.108 h1.34
  text "Top Layer - Bottom Layer" at 206.406,179.108 h1.34
  text "16" at 170.638,176.331 h1.34
  text "39.37mil (1.000mm)" at 178.047,176.331 h1.34
  text "PTH" at 192.251,176.331 h1.34
  text "Round" at 198.034,176.331 h1.34
  text "Top Layer - Bottom Layer" at 206.406,176.331 h1.34
  text "C" at 163.344,176.078 h1.23
  text "5" at 170.638,173.555 h1.34
  text "40.00mil (1.016mm)" at 178.047,173.555 h1.34
  text "PTH" at 192.251,173.555 h1.34
  text "Round" at 198.034,173.555 h1.34
  text "Top Layer - Bottom Layer" at 206.406,173.555 h1.34
  text "36" at 170.638,170.778 h1.34
  text "40.16mil (1.020mm)" at 178.047,170.778 h1.34
  text "PTH" at 192.251,170.778 h1.34
  text "Round" at 198.034,170.778 h1.34
  text "Top Layer - Bottom Layer" at 206.406,170.778 h1.34
  text "2" at 170.638,168.002 h1.34
  text "43.31mil (1.100mm)" at 178.047,168.002 h1.34
  text "PTH" at 192.251,168.002 h1.34
  text "Round" at 198.034,168.002 h1.34
  text "Top Layer - Bottom Layer" at 206.406,168.002 h1.34
  text "2" at 170.638,165.225 h1.34
  text "47.24mil (1.200mm)" at 178.047,165.225 h1.34
  text "PTH" at 192.251,165.225 h1.34
  text "Round" at 198.034,165.225 h1.34
  text "Top Layer - Bottom Layer" at 206.406,165.225 h1.34
  text "A" at 163.344,164.971 h1.23
  text "1" at 170.638,162.449 h1.34
  text "51.18mil (1.300mm)" at 178.047,162.449 h1.34
  text "PTH" at 192.251,162.449 h1.34
  text "Round" at 198.034,162.449 h1.34
  text "Top Layer - Bottom Layer" at 206.406,162.449 h1.34
  text "7" at 170.638,159.672 h1.34
  text "59.06mil (1.500mm)" at 178.047,159.672 h1.34
  text "PTH" at 192.251,159.672 h1.34
  text "Round" at 198.034,159.672 h1.34
  text "Top Layer - Bottom Layer" at 206.406,159.672 h1.34
  text "2" at 170.638,156.896 h1.34
  text "66.93mil (1.700mm)" at 178.047,156.896 h1.34
  text "PTH" at 192.251,156.896 h1.34
  text "Round" at 198.034,156.896 h1.34
  text "Top Layer - Bottom Layer" at 206.406,156.896 h1.34
  text "12" at 170.638,154.119 h1.34
  text "75.00mil (1.905mm)" at 178.047,154.119 h1.34
  text "PTH" at 192.251,154.119 h1.34
  text "Round" at 198.034,154.119 h1.34
  text "Top Layer - Bottom Layer" at 206.406,154.119 h1.34
  text "8" at 170.638,151.343 h1.34
  text "78.74mil (2.000mm)" at 178.047,151.343 h1.34
  text "PTH" at 192.251,151.343 h1.34
  text "Round" at 198.034,151.343 h1.34
  text "Top Layer - Bottom Layer" at 206.406,151.343 h1.34
  text "9" at 170.638,148.566 h1.34
  text "98.43mil (2.500mm)" at 178.047,148.566 h1.34
  text "PTH" at 192.251,148.566 h1.34
  text "Round" at 198.034,148.566 h1.34
  text "Top Layer - Bottom Layer" at 206.406,148.566 h1.34
  text "B" at 163.344,148.312 h1.23
  text "16" at 170.638,145.79 h1.34
  text "110.24mil (2.800mm)" at 178.047,145.79 h1.34
  text "PTH" at 192.251,145.79 h1.34
  text "Round" at 198.034,145.79 h1.34
  text "Top Layer - Bottom Layer" at 206.406,145.79 h1.34
  text "2" at 170.638,143.013 h1.34
  text "118.11mil (3.000mm)" at 178.047,143.013 h1.34
  text "PTH" at 192.251,143.013 h1.34
  text "Round" at 198.034,143.013 h1.34
  text "Top Layer - Bottom Layer" at 206.406,143.013 h1.34
  text "D" at 163.344,142.759 h1.23
  text "673 Total" at 170.638,140.236 h1.34
  text ".Layer_Name" at 14.656,-21.806 h1.52
M17 Embedded Cavity:
  text ".Layer_Name" at 14.656,-21.806 h1.52
M18 Embedded Assembly:
  text ".Layer_Name" at 14.656,-21.806 h1.52
M19 Embedded Keepout:
  circle w2: c202.5,13 r3.55
  circle w2: c167,16.75 r3.55
  circle w2: c166,59.5 r3.55
  circle w2: c167,26.75 r2.6
  circle w2: c202.5,23 r2.6
  circle w2: c201.75,69.5 r2.6
  circle w2: c201.75,59.5 r3.55
  circle w2: c166,69.5 r2.6
  circle w2: c110.85,77.19 r3.6
  circle w2: c110.85,37.82 r3.5
  circle w3.5: c84.5,126.75 r2.6
  circle w3.5: c28.25,66.25 r3.2
  circle w3.5: c30.476,70.5 r3.2
  circle w3.5: c80.25,89 r2.552
  circle w3.5: c22.34,11.928 r2.5
  circle w3.5: c85.5,81.9 r2.5
  lines w2: 105.2,44.7 107.6,47.1 118.6,47.1 121.4,44.3 ; 117.5,74 125.7,65.8 156.151,65.8 ; 148,9.553 148,31.253 150.4,33.653 157.274,33.653 160.953,37.365 160.953,54 ; 148.129,24.6 148.129,23.371 148.3,23.2 162.129,23.2 164.129,25.2 ; 169.5,19.3 172.1,16.7 ; 172.2,16.6 215.5,16.6 ; 198.2,59.9 198.2,42.696 208.396,32.5 215.5,32.5
  lines w3.2: 21,30.4 22.1,29.3 43.7,29.3 53.7,39.3 55.7,39.3 ; 22.7,43 30.6,50.9 36.283,50.9 42.3,56.917 42.3,81.8 47.99,87.49 47.99,96.71 ; 52.6,2.8 52.6,19.8 56.5,23.7 67.2,23.7 70,20.9 ; 71.8,40.4 71.8,34.5 68.6,31.3 58.2,31.3 55.7,33.8 55.7,86.4 60.1,90.8 60.1,96.1 62.5,98.5 77.3,98.5
  lines w5: 180.5,129.5 180.5,115.25 183.75,112 220.358,112
  text ".Layer_Name" at 14.656,-21.806 h1.52

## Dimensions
220,-0.75 to 20,0 on M2 Board Dimensions
220,0 to 20,0 on M2 Board Dimensions
0,-10.16 to 25.4,-10.16 on M2 Board Dimensions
